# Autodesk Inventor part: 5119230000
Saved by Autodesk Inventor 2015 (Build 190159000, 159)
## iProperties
Created: 2020-07
Part Number: 5119230000
Checked By: TraceParts S.A.
Material: Generic
Catalog Web Link: www.traceparts.com
Document SubType Name: Modeling
Designer: TraceParts
Density: 1 g/cm^3
Appearance: Default
Company: TraceParts S.A.
Author: TraceParts
REFERENCE: 5119230000
DESIGN: HIB-1000 P 0,75KW (230V 50HZ) - 5119230000
SUPPLIER: Soler & Palau
TraceParts.PartNumber: 10-20122018-119595
TraceParts.PartTitle: HIB-P/HIT-P
TraceParts.InstanceId: 10-20122018-119595CKLNEXHKIUM7G9SFESOFMLKUQ
TraceParts.PartStatus: Published
TraceParts.PartVersion: 1.0.2
TRACEPARTS: TRACEPARTS
TraceParts.PartLanguage: en
TraceParts.ClassPath: SOLER_PALAU:10-20122018-119595
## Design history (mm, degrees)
feature "5119230000"
body "Solid1"
